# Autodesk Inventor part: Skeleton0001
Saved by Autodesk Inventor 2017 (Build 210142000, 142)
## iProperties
Created: 2020-07
Part Number: Skeleton0001
Material: Generic
Document SubType Name: Modeling
Designer: X
Density: 1 g/cm^3
Appearance: Default
_SkeletonDoc: Frame Skeleton File
_Version: 15.0.0
Author: X
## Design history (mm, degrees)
sketch "Szkielet odniesienia"
